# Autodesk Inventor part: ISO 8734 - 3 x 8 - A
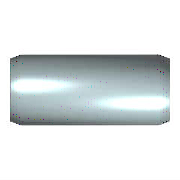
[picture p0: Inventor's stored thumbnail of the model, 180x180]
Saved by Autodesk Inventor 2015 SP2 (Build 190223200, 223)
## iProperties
Created: 2012-02
Part Number: ISO 8734 - 3 x 8 - A
Material: Stahl
Description: Zylinderstift
Document SubType Name: Modeling
Standard: ISO 8734
Designer: rYan
Standards Organization: DIN
Language: de-DE
Size Designation: 3 x 8 - A
Categories: <MemberInstance><Categories><Category DisplayName="Verbindungselemente" InternalName="e4da775c-781d-43d5-af7c-5136215cf5a6" Mnemonic="FSTN"><Category DisplayNam
Density: 7.85 g/cm^3
Mass: 0.439099 g
Surface Area: 0.870195 cm^2
Volume: 0.0559361 cm^3
Appearance: Platte
IsCustomPart: 0
Author: rYan
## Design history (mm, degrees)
sketch "Skizze"
  geometry: C1 r 1.5 at (0, 0); 1 further point
  constraints: 1 centre point, 1 coincident
  dimensions: "d1" = 3 diameter of C1 (= NND)
extrude "Körper" new body sketch "Skizze" distance "d2" = 8 (= NLG); taper "d3" = 0 deg
body "Solid1"
chamfer "Fase1" distance "d4" = 0.5 (= PHH); stored, may be unused: angle "d5" = 15 deg (= FAWI), second distance "d11" = 0.5 (= PHH)
chamfer "Fase2" distance "d8" = 0.5 (= PHH); stored, may be unused: angle "d9" = 15 deg (= FAWI), second distance "d12" = 0.5 (= PHH)
other parameters: "NND" = 3 [user parameter; used in 1 equation term], "NLG" = 8 [user parameter; used in 1 equation term], "PHH" = 0.5 [user parameter; used in 5 equation terms], "FAWI" = 15 deg [user parameter; used in 2 equation terms], "d13" = 0, "d15" = 0, "d16" = 0, "PHH2" = 0.5 (= PHH) [user parameter], "FAWI2" = 15 deg [user parameter]
